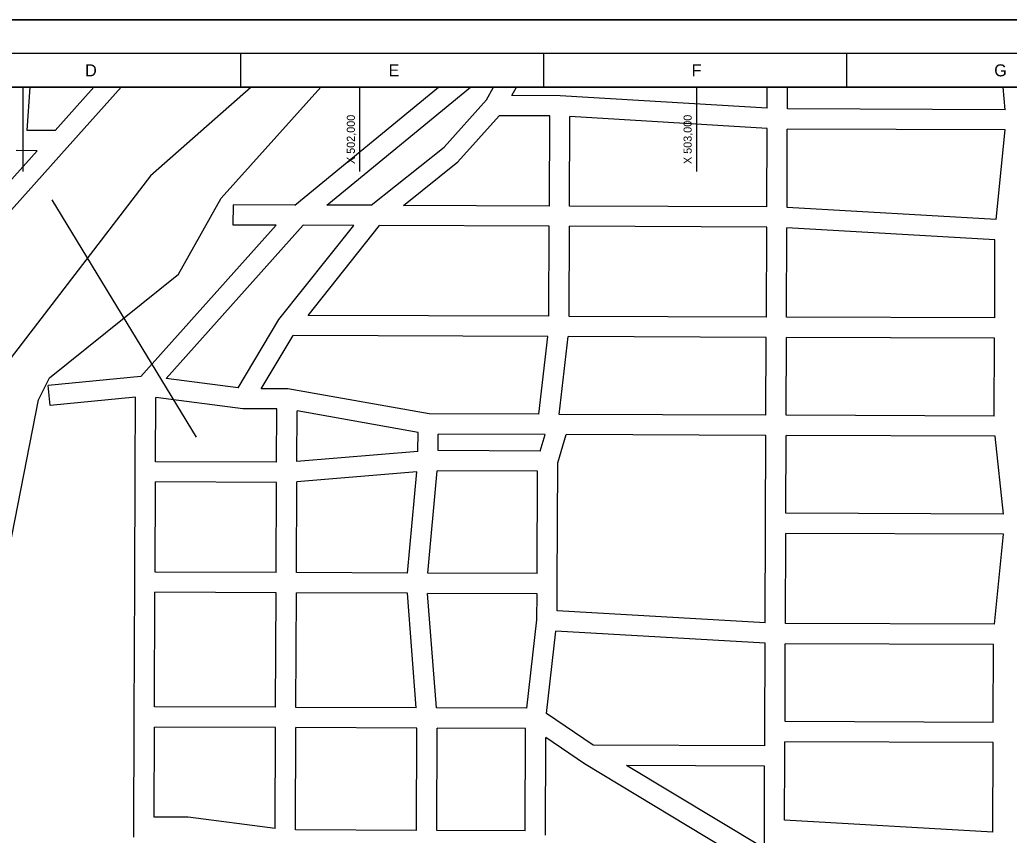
# Model space of a CAD drawing. Extents: x 497696 to 505896, y 1319278 to 1325078.
# Drawn here: x 500990 to 503928, y 1322658 to 1325078 of the extents above; entities that cross this region are included whole.
import ezdxf

# ---------------------------------------------------------------- set-up
doc = ezdxf.new("R2010")
doc.units = 0
for name, color, linetype in [('G-ANNO-TTLB', 7, 'Continuous'), ('Level 1', 7, 'Continuous'), ('Level 2', 7, 'Continuous'), ('Level 3', 7, 'Continuous'), ('Level 32', 7, 'Continuous'), ('Level 5', 7, 'Continuous'), ('Level 58', 7, 'Continuous')]:
    doc.layers.add(name, color=color, linetype=linetype)

msp = doc.modelspace()

# ---------------------------------------------------------------- linework, layer by layer
at = {"layer": 'G-ANNO-TTLB'}
for p, q in [((505796.2, 1324977.9), (497796.2, 1324977.9)), ((501646.2, 1324877.9), (501646.2, 1324977.9)), ((502546.2, 1324877.9), (502546.2, 1324977.9)), ((503446.2, 1324877.9), (503446.2, 1324977.9)), ((498046.2, 1324877.9), (505696.2, 1324877.9))]:
    msp.add_line(p, q, dxfattribs=at)
for points in [[(497696.2, 1319277.9), (505896.2, 1319277.9), (505896.2, 1325077.9), (497696.2, 1325077.9)], [(497696.2, 1319277.9), (505896.2, 1319277.9), (505896.2, 1325077.9), (497696.2, 1325077.9)], [(497696.2, 1325077.9), (505896.2, 1325077.9), (505896.2, 1319277.9), (497696.2, 1319277.9)]]:
    msp.add_lwpolyline(points, close=True, dxfattribs=at)
at = {"layer": 'Level 1'}
for p, q in [((501646.2, 1324877.9), (501646.2, 1324977.9)), ((502546.2, 1324877.9), (502546.2, 1324977.9)), ((503446.2, 1324877.9), (503446.2, 1324977.9))]:
    msp.add_line(p, q, dxfattribs=at)
for points in [[(497796.2, 1319377.9), (505796.2, 1319377.9), (505796.2, 1324977.9), (497796.2, 1324977.9)], [(498046.2, 1319477.9), (505696.2, 1319477.9), (505696.2, 1324877.9), (498046.2, 1324877.9)]]:
    msp.add_lwpolyline(points, close=True, dxfattribs=at)
at = {"layer": 'Level 2'}
for p, q in [((501000, 1324627.9), (501000, 1324877.9)), ((502000, 1324627.9), (502000, 1324877.9)), ((503000, 1324627.9), (503000, 1324877.9))]:
    msp.add_line(p, q, dxfattribs=at)
at = {"layer": 'Level 32'}
for p, q in [((501011.8, 1324749.6), (501021.2, 1324877.9)), ((502375.5, 1324840.7), (502396.3, 1324877.9)), ((502451.2, 1324853), (502465.1, 1324877.9)), ((502594.7, 1324852.4), (502451.2, 1324853)), ((503209.3, 1324815.4), (503209.5, 1324877.9)), ((503269.3, 1324813.5), (503269.5, 1324877.9)), ((503916.3, 1324811), (503909.9, 1324877.9)), ((503209.3, 1324815.4), (502594.7, 1324852.4)), ((503916.3, 1324811), (503269.3, 1324813.5)), ((502563.6, 1324792.6), (502413.5, 1324793.2)), ((502562.6, 1324525.4), (502563.6, 1324792.6)), ((502622.6, 1324525.1), (502623.6, 1324790.6)), ((503209, 1324755.3), (502623.6, 1324790.6)), ((501095.2, 1324749.2), (501011.8, 1324749.6)), ((503208.1, 1324522.9), (503209, 1324755.3)), ((503268.1, 1324521.1), (503269, 1324753.5)), ((503916, 1324751), (503269, 1324753.5)), ((503888.8, 1324485.4), (503916, 1324751)), ((500804.3, 1324424.1), (501041.7, 1324689.4)), ((500840.2, 1324374.3), (501130.9, 1324699.2)), ((501041.7, 1324689.4), (500979.4, 1324689.7)), ((501624, 1324469), (501624.3, 1324529)), ((501807.2, 1324528.3), (501624.3, 1324529)), ((502033.3, 1324527.4), (501901.4, 1324527.9)), ((502562.6, 1324525.4), (502129, 1324527.1)), ((503208.1, 1324522.9), (502622.6, 1324525.1)), ((503888.8, 1324485.4), (503268.1, 1324521.1)), ((501349.4, 1324019.8), (501751, 1324468.5)), ((501424.3, 1324013.5), (501831.2, 1324468.2)), ((501751, 1324468.5), (501624, 1324469)), ((501759.5, 1324188.3), (501981.8, 1324467.6)), ((501981.8, 1324467.6), (501831.2, 1324468.2)), ((501846.3, 1324201), (502058.2, 1324467.3)), ((502562.4, 1324465.4), (502058.2, 1324467.3)), ((502561.3, 1324198.2), (502562.4, 1324465.4)), ((502621.3, 1324197.9), (502622.4, 1324465.1)), ((503207.9, 1324462.9), (502622.4, 1324465.1)), ((503206.9, 1324195.7), (503207.9, 1324462.9)), ((503266.9, 1324195.4), (503267.9, 1324461)), ((503885.6, 1324425.5), (503267.9, 1324461)), ((503884.7, 1324193.1), (503885.6, 1324425.5)), ((501638.6, 1323985.8), (501759.5, 1324188.3)), ((502561.3, 1324198.2), (501846.3, 1324201)), ((503206.9, 1324195.7), (502621.3, 1324197.9)), ((503884.7, 1324193.1), (503266.9, 1324195.4)), ((501707, 1323983.4), (501801.3, 1324141.1)), ((502557.6, 1324138.2), (501801.3, 1324141.1)), ((502531.1, 1323907.4), (502557.6, 1324138.2)), ((502591.4, 1323907.2), (502617.9, 1324138)), ((503206.6, 1324135.7), (502617.9, 1324138)), ((503205.7, 1323904.8), (503206.6, 1324135.7)), ((503265.7, 1323904.6), (503266.6, 1324135.4)), ((503884.5, 1324133.1), (503266.6, 1324135.4)), ((503883.6, 1323902.2), (503884.5, 1324133.1)), ((501349.4, 1324019.8), (501074.5, 1323992.7)), ((501638.6, 1323985.8), (501424.3, 1324013.5)), ((501080.4, 1323933), (501074.5, 1323992.7)), ((501786.1, 1323983.1), (501707, 1323983.4)), ((502205.4, 1323908.7), (501786.1, 1323983.1)), ((501333.8, 1323958), (501080.4, 1323933)), ((501332.9, 1323736.7), (501333.8, 1323958)), ((501393.1, 1323766.5), (501393.8, 1323957)), ((501652.3, 1323923.6), (501393.8, 1323957)), ((501753.3, 1323923.2), (501652.3, 1323923.6)), ((501752.7, 1323765.1), (501753.3, 1323923.2)), ((501812.7, 1323767.5), (501813.3, 1323917.3)), ((502172.6, 1323853.6), (501813.3, 1323917.3)), ((502531.1, 1323907.4), (502205.4, 1323908.7)), ((503205.7, 1323904.8), (502591.4, 1323907.2)), ((503883.6, 1323902.2), (503265.7, 1323904.6)), ((502172.4, 1323797.3), (502172.6, 1323853.6)), ((502232.4, 1323799.5), (502232.6, 1323848.6)), ((502549.8, 1323847.4), (502232.6, 1323848.6)), ((502535.1, 1323798.4), (502549.8, 1323847.4)), ((502587.4, 1323763.8), (502612.4, 1323847.1)), ((503205.5, 1323844.8), (502612.4, 1323847.1)), ((503204.5, 1323584), (503205.5, 1323844.8)), ((503264.6, 1323613.8), (503265.5, 1323844.6)), ((503886.5, 1323842.2), (503265.5, 1323844.6)), ((503911.2, 1323611.3), (503886.5, 1323842.2)), ((502172.4, 1323797.3), (501812.7, 1323767.5)), ((502535.1, 1323798.4), (502232.4, 1323799.5)), ((501752.7, 1323765.1), (501393.1, 1323766.5)), ((501331.7, 1323409.5), (501332.9, 1323736.7)), ((502169.1, 1323736.8), (501812.5, 1323707.3)), ((502141.3, 1323436.3), (502169.1, 1323736.8)), ((502201.5, 1323436.1), (502229.7, 1323739.6)), ((502527.3, 1323738.4), (502229.7, 1323739.6)), ((502526.1, 1323434.8), (502527.3, 1323738.4)), ((502586, 1323404.6), (502587.4, 1323763.8)), ((501811.4, 1323437.6), (501812.5, 1323707.3)), ((501391.8, 1323439.3), (501392.8, 1323706.5)), ((501752.4, 1323705.1), (501392.8, 1323706.5)), ((501751.4, 1323437.9), (501752.4, 1323705.1)), ((503911.2, 1323611.3), (503264.6, 1323613.8)), ((503203.4, 1323288.4), (503204.5, 1323584)), ((503263.3, 1323286.6), (503264.4, 1323553.8)), ((503911.4, 1323551.3), (503264.4, 1323553.8)), ((503884, 1323284.2), (503911.4, 1323551.3)), ((501751.4, 1323437.9), (501391.8, 1323439.3)), ((502141.3, 1323436.3), (501811.4, 1323437.6)), ((502526.1, 1323434.8), (502201.5, 1323436.1)), ((501330.1, 1323009.6), (501331.7, 1323409.5)), ((502585.6, 1323324), (502586, 1323404.6)), ((501390.2, 1323039.4), (501391.5, 1323379.3)), ((501751.2, 1323377.9), (501391.5, 1323379.3)), ((501749.8, 1323038), (501751.2, 1323377.9)), ((501809.8, 1323037.7), (501811.2, 1323377.6)), ((502140.8, 1323376.3), (501811.2, 1323377.6)), ((502166.9, 1323036.3), (502140.8, 1323376.3)), ((502227.1, 1323036.1), (502201, 1323376.1)), ((502525.8, 1323374.8), (502201, 1323376.1)), ((502525.5, 1323297.4), (502525.8, 1323374.8)), ((502495.4, 1323035), (502525.5, 1323297.4)), ((503203.4, 1323288.4), (502585.6, 1323324)), ((503884, 1323284.2), (503263.3, 1323286.6)), ((502554, 1323019.5), (502582.1, 1323264.1)), ((503203.1, 1323228.4), (502582.1, 1323264.1)), ((503202.1, 1322965.9), (503203.1, 1323228.4)), ((503262.2, 1322995.7), (503263.1, 1323226.6)), ((503881, 1323224.2), (503263.1, 1323226.6)), ((503880.1, 1322993.3), (503881, 1323224.2)), ((501749.8, 1323038), (501390.2, 1323039.4)), ((502166.9, 1323036.3), (501809.8, 1323037.7)), ((502495.4, 1323035), (502227.1, 1323036.1)), ((501328.7, 1322652.4), (501330.1, 1323009.6)), ((502692.4, 1322925.2), (502554, 1323019.5)), ((501388.9, 1322712.2), (501390, 1322979.4)), ((501749.6, 1322978), (501390, 1322979.4)), ((501748.4, 1322678.4), (501749.6, 1322978)), ((501808.4, 1322674.2), (501809.6, 1322977.7)), ((502169.2, 1322976.3), (501809.6, 1322977.7)), ((502168, 1322672.8), (502169.2, 1322976.3)), ((502228, 1322672.5), (502229.2, 1322976.1)), ((502492, 1322975.1), (502229.2, 1322976.1)), ((502490.8, 1322671.5), (502492, 1322975.1)), ((503880.1, 1322993.3), (503262.2, 1322995.7)), ((502550.8, 1322658.4), (502551.9, 1322948.3)), ((502666.9, 1322870), (502551.9, 1322948.3)), ((503201.9, 1322923.2), (503202.1, 1322965.9)), ((503201.9, 1322923.2), (502692.4, 1322925.2)), ((503261.8, 1322893), (503262, 1322935.7)), ((503879.8, 1322933.3), (503262, 1322935.7)), ((503878.8, 1322667.8), (503879.8, 1322933.3)), ((503261.1, 1322703.3), (503261.8, 1322893)), ((503206.9, 1322545.1), (502666.9, 1322870)), ((503201.7, 1322863.2), (502791.9, 1322864.8)), ((503200.8, 1322618.9), (502791.9, 1322864.8)), ((503201, 1322675.1), (503201.7, 1322863.2)), ((501489.9, 1322711.8), (501388.9, 1322712.2)), ((501748.4, 1322678.4), (501489.9, 1322711.8)), ((503878.8, 1322667.8), (503261.1, 1322703.3)), ((502168, 1322672.8), (501808.4, 1322674.2)), ((502490.8, 1322671.5), (502228, 1322672.5)), ((503200.8, 1322618.9), (503201, 1322675.1))]:
    msp.add_line(p, q, dxfattribs=at)
for points in [[(501095.2, 1324749.2), (501210.4, 1324877.9)], [(501130.9, 1324699.2), (501290.9, 1324877.9)], [(501807.2, 1324528.3), (502233.8, 1324877.9)], [(501901.4, 1324527.9), (502328.4, 1324877.9)], [(502033.3, 1324527.4), (502249.7, 1324700.2), (502375.5, 1324840.7)], [(502129, 1324527.1), (502291.1, 1324656.4), (502413.5, 1324793.2)]]:
    msp.add_lwpolyline(points, dxfattribs=at)
at = {"layer": 'Level 5'}
for points in [[(501677.2, 1324877.9), (501378.4, 1324614.6), (500725.8, 1323766.4), (500625.2, 1323558.4), (500565.9, 1323241.9), (500572.6, 1322708.4), (500738.3, 1322374.6), (500985.2, 1322032), (501020.7, 1321975.5), (501090.8, 1321884.7), (501394.4, 1321835.2), (501726.7, 1321794.1), (502293.5, 1321269.9), (502409.4, 1320994.5), (502987.7, 1320510.5), (503056.9, 1320142.4), (503189.4, 1319858.7), (503438.4, 1319516.2), (503472.5, 1319477.9)], [(504107.7, 1319477.9), (503822.6, 1319798.4), (503531.7, 1320041), (503232.9, 1320458.6), (503199.8, 1320550.4), (502737.7, 1321243.7), (502440.6, 1321661.5), (502255.8, 1321845.1), (502052.9, 1321934.2), (501254.5, 1322198), (501046.8, 1322407), (500972.3, 1322582.2), (500898.1, 1322849.2), (500933, 1323374.1), (501045.4, 1323950.4), (501078.5, 1324015.1), (501460.9, 1324322.7), (501588.1, 1324548.9), (501884.4, 1324877.9)]]:
    msp.add_lwpolyline(points, dxfattribs=at)
at = {"layer": 'Level 58'}
msp.add_line((501084.9, 1324543.3), (501513.6, 1323839.6), dxfattribs=at)

# ---------------------------------------------------------------- texts
at = {"layer": 'G-ANNO-TTLB'}
for s, p in [('D', (501184.2, 1324910.1)), ('E', (502085, 1324910.1)), ('F', (502985, 1324910.1)), ('G', (503883.4, 1324910.1))]:
    msp.add_text(s, height=35.7, dxfattribs=at).set_placement(p)
at = {"layer": 'Level 3'}
for s, p in [('X 502,000', (501985, 1324649.9)), ('X 503,000', (502985, 1324649.9))]:
    msp.add_text(s, height=24, rotation=90, dxfattribs=at).set_placement(p)

doc.saveas('drawing.dxf')
